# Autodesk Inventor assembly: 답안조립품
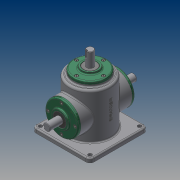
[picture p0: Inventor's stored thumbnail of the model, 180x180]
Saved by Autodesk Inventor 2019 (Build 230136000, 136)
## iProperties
Created: 2019-03
Part Number: 답안조립품
Material: 일반
Document SubType Name: Assembly
Designer: PC312-08
Author: PC312-08
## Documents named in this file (16)
- C:\Users\PC312-08\Desktop\490314V1012\답안조립품.iam
- C:\Users\PC312-08\Desktop\490314V1012\본체.ipt
- C:\Users\PC312-08\Desktop\490314V1012\커버.ipt
- C:\Users\PC312-08\Desktop\490314V1012\오일 실.ipt
- 오일 실.ipt
- C:\Users\PC312-08\Desktop\490314V1012\베어링 6203.ipt
- C:\Users\PC312-08\Desktop\490314V1012\메인 축.ipt
- 메인 축.ipt
- C:\Users\PC312-08\Desktop\490314V1012\서브 축.ipt
- 서브 축.ipt
- C:\Users\PC312-08\Desktop\490314V1012\키 5x5.ipt
- C:\Users\PC312-08\Desktop\490314V1012\키 4x4.ipt
- C:\Users\PC312-08\Desktop\490314V1012\메인 베벨기어.ipt
- C:\Users\PC312-08\Desktop\490314V1012\서브 베벨기어.ipt
- C:\Users\PC312-08\Desktop\490314V1012\볼트 M4.ipt
- 볼트 M4.ipt
